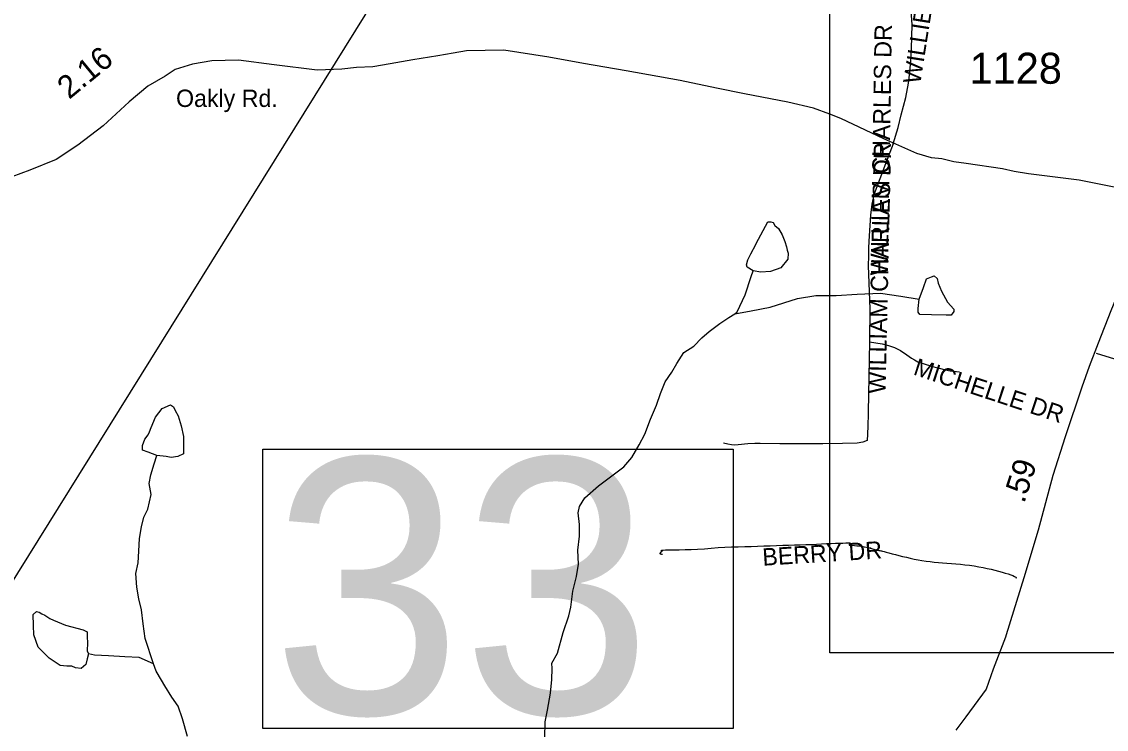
# Model space of a CAD drawing. Extents: x 1950930 to 2061844, y 904556 to 1017002.
# Drawn here: x 2005783 to 2011726, y 917674 to 921551 of the extents above; entities that cross this region are included whole.
import ezdxf

# ---------------------------------------------------------------- set-up
doc = ezdxf.new("R2010")
doc.units = 0
for name, color, linetype in [('Exist Hydrographic Creek Single Shore', 7, 'Continuous'), ('Exist Hydrographic Misc Water Feature', 7, 'Continuous'), ('Exist Road Non-System Type 51', 7, 'Continuous'), ('Exist Road Non-System Type 51 Label', 7, 'Continuous'), ('Exist Road Primary US Structure Standard Bridge CELL', 7, 'Continuous'), ('Exist Road Secondary Structure Standard Bridge Number Label', 7, 'Continuous'), ('Exist Road Secondary Type 41 Attributed', 7, 'Continuous'), ('Exist Road Secondary Type 51 Attributed', 7, 'Continuous'), ('Exist Road Secondary Type 51 Label', 7, 'Continuous'), ('Exist Road Secondary Type 51 Number Label', 7, 'Continuous'), ('Map Preparation Inset Cut Line', 7, 'Continuous')]:
    doc.layers.add(name, color=color, linetype=linetype)

msp = doc.modelspace()

# ---------------------------------------------------------------- linework, layer by layer
at = {"layer": 'Exist Hydrographic Creek Single Shore'}
for points in [[(2006505.8, 918031.9), (2006459.5, 918172), (2006449.7, 918251.9), (2006439.4, 918328), (2006425.6, 918388), (2006413.4, 918451.9), (2006409.4, 918527.8), (2006421.5, 918586), (2006425.4, 918649.9), (2006429.2, 918720), (2006439.3, 918783.8), (2006453.2, 918836), (2006475.1, 918879.9), (2006493.2, 918959.9), (2006481, 919019.9), (2006491.1, 919067.9), (2006509.1, 919127.9), (2006522.9, 919173.9)], [(2006691.9, 917633.9), (2006664.1, 917732), (2006639.9, 917800.1), (2006605.8, 917850), (2006567.7, 917911.8), (2006549.6, 917944), (2006519.8, 917991.9), (2006505.8, 918031.9)]]:
    msp.add_lwpolyline(points, dxfattribs=at)
at = {"layer": 'Exist Hydrographic Misc Water Feature'}
for points in [[(2009790.3, 920186.1), (2009758.5, 920206.1), (2009754.5, 920218), (2009762.3, 920246.1), (2009778.4, 920278.2), (2009806.4, 920330.2), (2009808.5, 920336), (2009858.3, 920430.2), (2009872.3, 920454.2), (2009888.3, 920454.2), (2009900.4, 920450.3), (2009910.3, 920434.3), (2009930.3, 920418.2), (2009950.2, 920382.3), (2009964.2, 920346.3), (2009974.5, 920318.2), (2009978.3, 920298.4), (2009982.3, 920282.2), (2009980.3, 920250.4), (2009942.5, 920202.3), (2009886.3, 920182.1), (2009832.4, 920178.3), (2009790.3, 920186.1)], [(2009690.6, 919950.2), (2009702.6, 919962.1), (2009746.5, 920054.1), (2009780.4, 920154.1), (2009790.3, 920186.1)], [(2010700.7, 920030.8), (2010724.6, 920094.6), (2010740.4, 920142.8), (2010768.5, 920152.8), (2010782.4, 920158.7), (2010798.5, 920143), (2010804.5, 920118.9), (2010822.7, 920074.9), (2010856.5, 920014.8), (2010890.5, 919975), (2010890.6, 919962.9), (2010876.7, 919942.8), (2010848.5, 919942.7), (2010768.4, 919944.7), (2010704.5, 919946.7), (2010694.6, 919958.7), (2010694.7, 919978.7), (2010700.7, 920030.8)], [(2009690.6, 919950.2), (2009710.7, 919954.1), (2009780.5, 919966.1), (2009884.6, 919986.3), (2010034.6, 920034.4), (2010134.7, 920050.3), (2010246.6, 920050.3), (2010360.6, 920058.5), (2010488.7, 920062.7), (2010600.6, 920046.6), (2010700.7, 920030.8)], [(2008649.9, 917627.3), (2008652, 917715.2), (2008663.9, 917779.3), (2008679.9, 917871.5), (2008687.7, 917947.5), (2008689.9, 918007.5), (2008687.8, 918035.4), (2008719.9, 918091.5), (2008749.7, 918203.5), (2008781.5, 918295.4), (2008791.7, 918343.4), (2008803.7, 918431.4), (2008823.4, 918511.4), (2008833.3, 918579.5), (2008831.3, 918655.3), (2008839.4, 918731.6), (2008839.4, 918795.6), (2008833.2, 918859.4), (2008839.2, 918895.4), (2008869.3, 918941.3), (2008943.2, 919007.4), (2009083.2, 919111.5), (2009126.9, 919163.8), (2009167.1, 919231.9), (2009196.9, 919291.6), (2009229.1, 919373.7), (2009260.8, 919449.8), (2009282.8, 919513.7), (2009308.8, 919577.8), (2009344.6, 919629.9), (2009372.8, 919677.9), (2009410.8, 919737.8), (2009466.7, 919774), (2009510.6, 919818.1), (2009550.7, 919854), (2009608.7, 919898.1), (2009658.6, 919930.2), (2009690.6, 919950.2)], [(2006522.9, 919173.9), (2006477, 919191.9), (2006445.1, 919204.1), (2006444.9, 919228), (2006458.8, 919263.8), (2006477, 919288.1), (2006482.9, 919304), (2006492.9, 919328.1), (2006516.7, 919384.1), (2006552.8, 919431.9), (2006598.8, 919451.9), (2006614.7, 919440.1), (2006624.8, 919420.2), (2006640.9, 919392), (2006656.8, 919336.2), (2006669.1, 919278.2), (2006669, 919276.2), (2006669.1, 919184), (2006638.9, 919168.2), (2006603.1, 919164), (2006574.9, 919167.9), (2006522.9, 919173.9)], [(2006149.6, 918087.8), (2006141.8, 918059.8), (2006135.6, 918029.7), (2006109.6, 918007.6), (2006077.8, 918011.5), (2006057.6, 918019.5), (2006029.8, 918019.7), (2005993.7, 918023.8), (2005939.7, 918059.7), (2005933.5, 918063.7), (2005873.7, 918123.4), (2005849.5, 918191.5), (2005847.7, 918243.4), (2005845.6, 918303.5), (2005863.7, 918319.5), (2005879.7, 918315.6), (2005893.6, 918307.4), (2005909.5, 918299.5), (2005937.7, 918281.6), (2005957.5, 918271.6), (2006023.6, 918243.7), (2006119.5, 918219.7), (2006141.6, 918207.8), (2006141.7, 918179.9), (2006143.6, 918147.7), (2006141.8, 918103.7), (2006149.6, 918087.8)], [(2006505.8, 918031.9), (2006427.8, 918068), (2006347.8, 918071.9), (2006259.6, 918075.7), (2006181.6, 918079.6), (2006149.6, 918087.8)]]:
    msp.add_lwpolyline(points, dxfattribs=at)
at = {"layer": 'Exist Road Non-System Type 51'}
for points in [[(2010559.1, 920881.2), (2010585.1, 920971), (2010602.6, 921040), (2010626.8, 921136.1), (2010641.6, 921213.4), (2010649.2, 921275), (2010656.4, 921360.5), (2010659.6, 921404.9), (2010661.9, 921533.3), (2010654.1, 921666.1), (2010646, 921757.1), (2010628.4, 921921.2), (2010620.2, 921983.6), (2010613.6, 922027.4), (2010605.4, 922066.9), (2010598.9, 922088.8), (2010580.2, 922103.1), (2010571.8, 922108.4)], [(2010559.1, 920881.2), (2010516.6, 920772.2), (2010455, 920606.9), (2010447.8, 920583.6), (2010440.5, 920551), (2010433.9, 920490), (2010426, 920378.2), (2010423, 920313.2), (2010423.6, 920268.5), (2010421.8, 920213.5), (2010430.2, 919978.4), (2010427.8, 919801.3), (2010427.8, 919796.7)], [(2010427.8, 919796.7), (2010425.4, 919605.8), (2010420.5, 919411.4), (2010421.1, 919402.1), (2010420, 919336.8), (2010418.1, 919290.9), (2010415.4, 919256.2)], [(2010427.8, 919796.7), (2010497.6, 919785.9), (2010533.2, 919777.5), (2010564.8, 919766.6), (2010598, 919749.9), (2010632.4, 919725.6), (2010659.1, 919707.5), (2010674.8, 919698.8), (2010694, 919688.1), (2010739.1, 919673.1), (2010781.2, 919660.5), (2010810.5, 919652.2), (2010844.4, 919644.2), (2010871.4, 919638.6), (2010922.1, 919633.3)], [(2011670, 919734.9), (2011936.6, 919653.1)], [(2010415.4, 919256.2), (2010391.5, 919246.8), (2010360.8, 919241.9), (2010279.8, 919239.5), (2010172.8, 919237.7), (2009936.5, 919237.4), (2009828.9, 919239.5), (2009800.5, 919239.5), (2009761.8, 919237.1), (2009708.6, 919232.9), (2009689.2, 919230.4), (2009671.8, 919232.9), (2009652.4, 919235.3), (2009628.9, 919240.8)], [(2009294.4, 918630.8), (2009292.4, 918631.4), (2009290, 918632), (2009287, 918632.6), (2009284.6, 918633.2), (2009283.1, 918634.4), (2009282.1, 918636.2), (2009282.1, 918638.1), (2009282.6, 918639.9), (2009284.1, 918642.3), (2009286, 918644.1), (2009288, 918646), (2009289.5, 918647.2), (2009290.5, 918647.8), (2009291.5, 918649), (2009291, 918649.6), (2009290.5, 918649), (2009290, 918649), (2009289.5, 918649), (2009289, 918649), (2009288.5, 918649), (2009288, 918649.6), (2009288, 918650.2), (2009288.5, 918652.1), (2009289, 918653.9), (2009289.5, 918655.1), (2009291, 918655.7), (2009297.9, 918656.3), (2009311.6, 918656.9), (2009331.8, 918657.5), (2009356.8, 918657.5), (2009385.8, 918657.6), (2009417.8, 918658.8), (2009451.6, 918659.4), (2009487, 918660.6), (2009523.9, 918663.1), (2009561.1, 918666.7), (2009599, 918669.8), (2009636.4, 918672.2), (2009672.8, 918672.8), (2009708.6, 918673.4), (2009744.9, 918674.6), (2009780.2, 918675.2), (2009815.1, 918676.5), (2009850.1, 918678.3), (2009885, 918679.6), (2009919.4, 918681.4), (2009952.8, 918682.6), (2009985.1, 918683.2), (2010017.6, 918683.8), (2010049, 918685.1), (2010079, 918685.7), (2010109, 918686.9), (2010138, 918688.1), (2010166, 918689.9), (2010192.5, 918691.2), (2010218.1, 918692.4), (2010241.6, 918693), (2010262.8, 918693.6), (2010281.9, 918694.2), (2010298.1, 918694.9), (2010310.4, 918694.9), (2010319.2, 918694.9), (2010324.2, 918694.2), (2010324.6, 918693.6), (2010323.2, 918692.4), (2010321.2, 918690.6), (2010319.2, 918688.8), (2010317.4, 918687), (2010316.9, 918685.1), (2010316.4, 918683.9), (2010316.9, 918683.3), (2010319.8, 918683.3), (2010325.1, 918683.3), (2010334.5, 918682.8), (2010345.8, 918681.5), (2010359.1, 918679.7), (2010372.4, 918678.5), (2010386.1, 918676.7), (2010399.4, 918674.2), (2010411.6, 918672.4), (2010421.5, 918670), (2010428.9, 918668.8), (2010433.2, 918667.6), (2010435.8, 918667), (2010434.2, 918667), (2010433.2, 918667), (2010432.2, 918667), (2010432.8, 918666.4), (2010434.8, 918665.8), (2010439.1, 918663.9), (2010445.1, 918662.8), (2010451.5, 918660.9), (2010458.4, 918659.7), (2010465.2, 918657.3), (2010472.1, 918656.1), (2010479, 918654.2), (2010484.9, 918653.1), (2010489.8, 918651.8), (2010494.8, 918651.2)], [(2010494.8, 918651.2), (2010500.6, 918649.4), (2010509, 918647.6), (2010520.8, 918644.6), (2010535, 918640.9), (2010552.1, 918636.1), (2010570.4, 918631.2), (2010590, 918626.4), (2010610.1, 918621.6), (2010630.8, 918616.7), (2010651.5, 918611.9), (2010672.6, 918607), (2010694.6, 918602.8), (2010716.2, 918598.5), (2010738.4, 918594.9), (2010760.5, 918592.5), (2010783.1, 918590.1), (2010805.8, 918587.6), (2010828.9, 918585.2), (2010852.4, 918583.4), (2010877, 918581.6), (2010901.5, 918580.4), (2010926.6, 918578), (2010951.6, 918575.6), (2010976.8, 918572.5), (2011001.8, 918568.9), (2011026.9, 918564.7), (2011050.9, 918560.4), (2011074, 918555.6), (2011095.6, 918550.8), (2011116.2, 918545.9), (2011135.9, 918540.4), (2011155.1, 918535.6), (2011172.8, 918530.1), (2011188.5, 918525.3), (2011202.8, 918520.4), (2011214.5, 918516.2), (2011223.9, 918511.9), (2011230.2, 918508.3), (2011232.8, 918505.9), (2011232.2, 918504.7), (2011231.8, 918502.9), (2011230.8, 918501.6)]]:
    msp.add_lwpolyline(points, dxfattribs=at)
at = {"layer": 'Exist Road Secondary Structure Standard Bridge Number Label'}
msp.add_line((2003522.3, 914932.5), (2007921.2, 921999.4), dxfattribs=at)
msp.add_lwpolyline([(2007104.2, 919208.5), (2009680.7, 919208.5), (2009680.7, 917679.2), (2007104.2, 917679.2)], close=True, dxfattribs=at)
at = {"layer": 'Exist Road Secondary Type 41 Attributed'}
msp.add_lwpolyline([(2012018.2, 920594.5), (2011578, 920682.1), (2011300.6, 920717.2), (2011220.8, 920729.2), (2011157.1, 920744.4), (2010958, 920773.8), (2010890, 920783.6), (2010824.1, 920799.6), (2010768.4, 920805.2), (2010688.5, 920828.8), (2010506.3, 920908.6), (2010271.2, 921020.2), (2010210.5, 921043.6), (2010120.9, 921078), (2009981.3, 921109.9), (2009744.4, 921155.5), (2009591.1, 921185.8), (2009391.4, 921229.1), (2009095.4, 921281.3), (2008861.3, 921321.1), (2008671.8, 921356.4), (2008425.7, 921394.1), (2008219.6, 921392), (2008146.5, 921378.1), (2008063, 921364.4), (2007926.4, 921341.6), (2007801.9, 921320.3), (2007707.7, 921303.7), (2007617.8, 921299.8), (2007537.8, 921291.6), (2007401.9, 921284.6), (2007165.8, 921315.3), (2006971.6, 921339.4), (2006825.7, 921337), (2006719.4, 921318.8), (2006623.8, 921288.4), (2006569.1, 921251.9), (2006475, 921197.2), (2006371.8, 921112.1), (2006229.8, 920980.7), (2006090.2, 920874.3), (2005971.7, 920795.3), (2005828.3, 920736.8), (2005629.4, 920663.9)], dxfattribs=at)
at = {"layer": 'Exist Road Secondary Type 51 Attributed'}
msp.add_lwpolyline([(2012018.2, 920594.5), (2011964.3, 920466.3), (2011902.5, 920330.4), (2011832.5, 920166.2), (2011750.5, 919966.2), (2011680.7, 919790.2), (2011632.8, 919662.2), (2011592.8, 919548.2), (2011501, 919276), (2011433.2, 919064), (2011353.4, 918764.9), (2011275, 918504.3), (2011178.2, 918191.1), (2011173.6, 918179), (2011106.9, 918002.9), (2011067.7, 917893.7), (2010955.5, 917743.1), (2010900.9, 917668.6)], dxfattribs=at)
at = {"layer": 'Map Preparation Inset Cut Line'}
for p, q in [((2010210.5, 921043.6), (2010210.5, 924342.6)), ((2015797, 918093.7), (2011107, 918093.7))]:
    msp.add_line(p, q, dxfattribs=at)
msp.add_lwpolyline([(2011107, 918093.7), (2010210.5, 918093.7), (2010210.5, 921043.6)], dxfattribs=at)

# ---------------------------------------------------------------- texts
at = {"layer": 'Exist Road Non-System Type 51 Label'}
for s, rotation, p in [('  WILLIE-MAE LN', 81.05006, (2010695.4, 921135.7)), ('  WILLIAM CHARLES DR', 89.05055, (2010527.7, 920089.3)), ('  WILLIAM CHARLES DR', 88.7054, (2010514.7, 919441.3)), ('  MICHELLE DR', 341.71925, (2010596.3, 919640.9)), ('  BERRY DR', 3.55332, (2009774, 918565.6))]:
    msp.add_text(s, height=95, rotation=rotation, dxfattribs=at).set_placement(p)
at = {"layer": 'Exist Road Primary US Structure Standard Bridge CELL'}
for s, rotation, p in [('2.16', 39.4965, (2006043.4, 921122.1)), ('.59', 72.2681, (2011276.2, 918908.2))]:
    msp.add_text(s, height=125, rotation=rotation, dxfattribs=at).set_placement(p)
at = {"layer": 'Exist Road Secondary Structure Standard Bridge Number Label'}
msp.add_text('33', height=1400, dxfattribs=at).set_placement((2007154.4, 917758.3))
at = {"layer": 'Exist Road Secondary Type 51 Label'}
msp.add_text('Oakly Rd.', height=95, dxfattribs=at).set_placement((2006628.9, 921083.7))
at = {"layer": 'Exist Road Secondary Type 51 Number Label'}
msp.add_text('1128', height=170, dxfattribs=at).set_placement((2010977, 921210.9))

doc.saveas('drawing.dxf')
